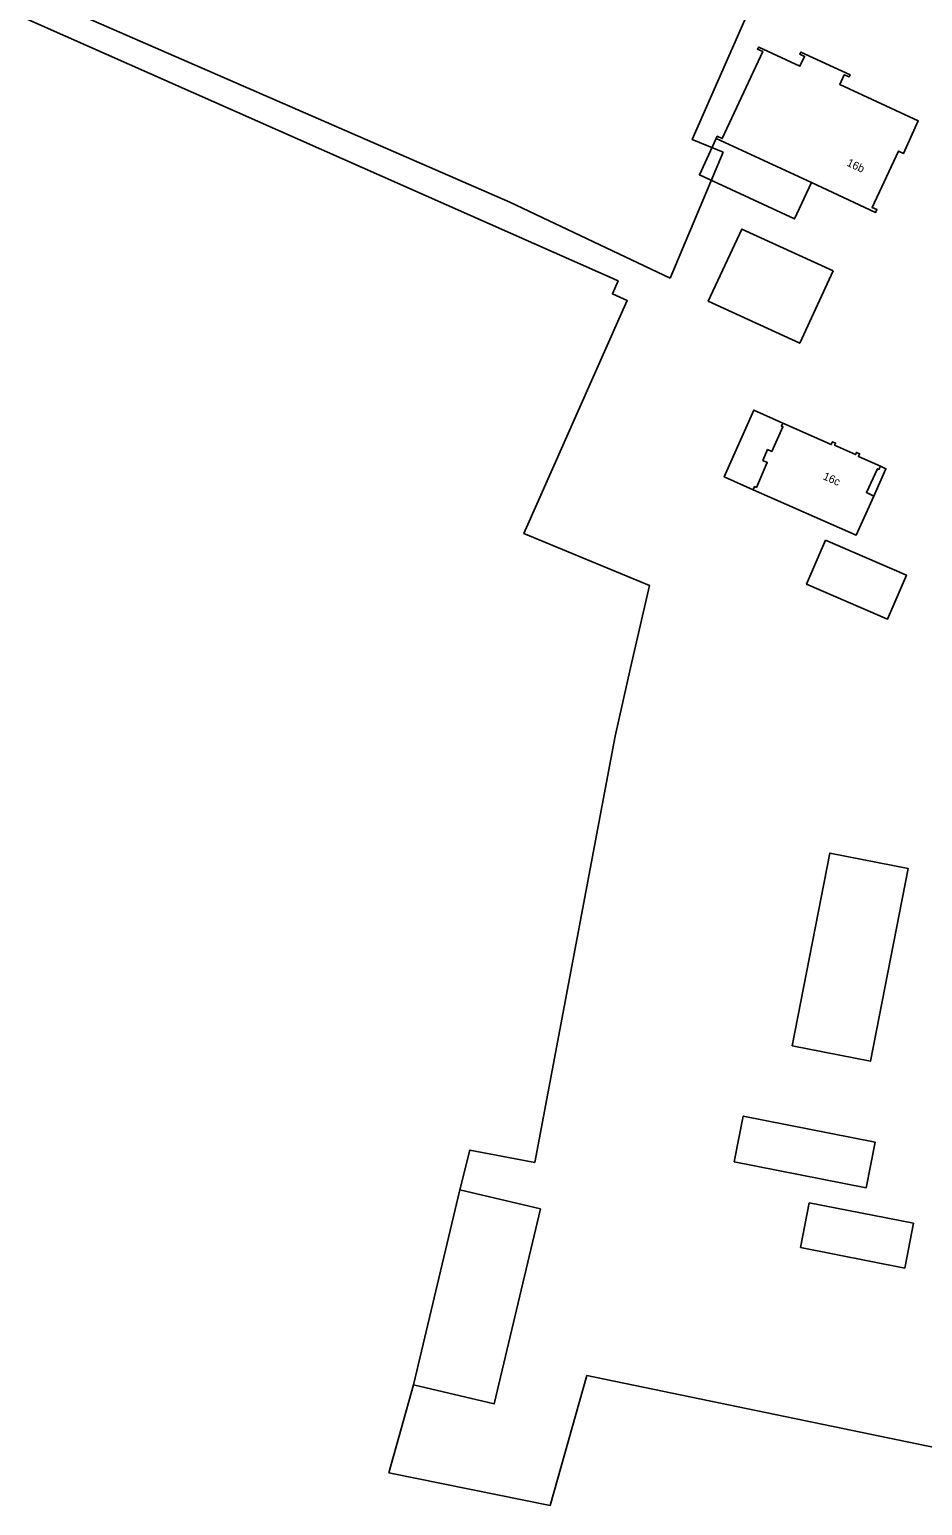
# Model space of a CAD drawing. Extents: x 136000 to 141000, y 400494 to 402006.
# Drawn here: x 137065.4 to 137177.1, y 401403.3 to 401587.8 of the extents above; entities that cross this region are included whole.
import ezdxf

# ---------------------------------------------------------------- set-up
doc = ezdxf.new("R2010")
doc.units = 0
for name, color, linetype in [('gg-afsc-draadraster', 7, 'Continuous'), ('gg-afsc-lijn draadraster', 7, 'Continuous'), ('gg-anno-huisnummerreeks BGT', 7, 'Continuous'), ('gg-bbg-bijgebouw', 7, 'Continuous'), ('gg-bbg-gedigitaliseerde bijgebouw', 7, 'Continuous'), ('gg-bbg-hoofdgebouw', 7, 'Continuous'), ('gg-bbg-luifel en loopbrug', 7, 'Continuous'), ('gg-bbg-open loods', 7, 'Continuous'), ('gg-knt-bronhoudergrens', 7, 'Continuous'), ('gt-bbg-plantopografie pand', 7, 'Continuous'), ('gt-grn-vlakafsluiter', 7, 'Continuous')]:
    doc.layers.add(name, color=color, linetype=linetype)

msp = doc.modelspace()

# ---------------------------------------------------------------- linework, layer by layer
at = {"layer": 'gg-afsc-draadraster'}
msp.add_line((137135.1, 401419.6), (137195.75, 401407.02), dxfattribs=at)
at = {"layer": 'gg-afsc-lijn draadraster'}
msp.add_line((137135.1, 401419.6), (137195.75, 401407.02), dxfattribs=at)
at = {"layer": 'gg-bbg-bijgebouw'}
msp.add_lwpolyline([(137165.9, 401557.62), (137161.72, 401548.59), (137150.29, 401553.83), (137154.47, 401562.85), (137165.9, 401557.62)], dxfattribs=at)
at = {"layer": 'gg-bbg-gedigitaliseerde bijgebouw'}
for points in [[(137160.76, 401460.78), (137170.56, 401458.86), (137175.29, 401482.94), (137165.49, 401484.87), (137160.76, 401460.78)], [(137161.8, 401435.57), (137162.9, 401441.16), (137175.94, 401438.6), (137174.84, 401433.01), (137161.8, 401435.57)]]:
    msp.add_lwpolyline(points, dxfattribs=at)
at = {"layer": 'gg-bbg-hoofdgebouw'}
msp.add_line((137151.28, 401574.17), (137163.18, 401568.65), dxfattribs=at)
for points in [[(137163.18, 401568.65), (137171.2, 401564.93), (137171.36, 401565.28), (137170.76, 401565.54), (137174.05, 401572.59), (137174.68, 401572.29), (137176.53, 401576.37), (137166.73, 401580.91), (137167.29, 401582.14), (137167.89, 401581.86), (137168.02, 401582.13), (137161.85, 401584.97), (137161.73, 401584.7), (137162.32, 401584.43), (137161.75, 401583.2), (137156.59, 401585.59), (137156.46, 401585.32), (137157.09, 401585.03), (137152.04, 401574.15), (137151.41, 401574.44), (137151.28, 401574.17)], [(137159.61, 401538.61), (137159.44, 401538.23), (137159.61, 401538.15), (137158.22, 401535.07), (137157.7, 401535.29), (137157.11, 401533.92), (137157.65, 401533.69), (137156.31, 401530.56), (137156.07, 401530.66), (137155.91, 401530.27)], [(137171.8, 401533.2), (137169.05, 401534.42), (137169.21, 401534.78), (137168.83, 401534.94), (137168.71, 401534.67), (137166.08, 401535.85), (137166.2, 401536.11), (137165.82, 401536.27), (137165.67, 401535.92), (137159.61, 401538.61)], [(137170.97, 401529.48), (137170.05, 401529.91), (137171.46, 401532.9), (137171.63, 401532.82), (137171.8, 401533.2)], [(137155.91, 401530.27), (137168.79, 401524.6), (137170.97, 401529.48)]]:
    msp.add_lwpolyline(points, dxfattribs=at)
at = {"layer": 'gg-bbg-luifel en loopbrug'}
for points in [[(137151.28, 401574.17), (137149.18, 401569.63), (137161.07, 401564.11), (137163.18, 401568.65)], [(137155.91, 401530.27), (137152.28, 401531.87), (137155.99, 401540.22), (137159.61, 401538.61)], [(137170.97, 401529.48), (137172.49, 401532.89), (137171.8, 401533.2)]]:
    msp.add_lwpolyline(points, dxfattribs=at)
at = {"layer": 'gg-bbg-open loods'}
msp.add_line((137119.23, 401442.8), (137113.43, 401418.4), dxfattribs=at)
for points in [[(137153.54, 401446.29), (137154.66, 401452), (137171.15, 401448.75), (137170.03, 401443.05), (137153.54, 401446.29)], [(137113.43, 401418.4), (137123.51, 401416.04), (137129.3, 401440.41), (137119.23, 401442.8)]]:
    msp.add_lwpolyline(points, dxfattribs=at)
at = {"layer": 'gg-knt-bronhoudergrens'}
for p, q in [((137152.13, 401572.45), (137145.53, 401556.71)), ((137138.63, 401499.47), (137128.61, 401446.22)), ((137130.51, 401403.34), (137135.1, 401419.6))]:
    msp.add_line(p, q, dxfattribs=at)
for points in [[(137040.75, 401603.11), (137035.6, 401605.35), (136954.37, 401641.77), (136916.84, 401660.23), (136915.67, 401657.84), (136997.85, 401618.86), (137139.02, 401556.38), (137138.3, 401554.75), (137140.14, 401553.93), (137139.26, 401551.95)], [(137138.63, 401499.47), (137140.57, 401508), (137142.92, 401518.32), (137127.23, 401524.8), (137139.26, 401551.95)], [(137119.23, 401442.8), (137120.48, 401447.75), (137128.61, 401446.22)], [(137113.43, 401418.4), (137110.35, 401407.4), (137130.51, 401403.34)]]:
    msp.add_lwpolyline(points, dxfattribs=at)
at = {"layer": 'gt-bbg-plantopografie pand'}
msp.add_lwpolyline([(137164.96, 401523.98), (137175.06, 401519.61), (137172.68, 401514.1), (137162.58, 401518.47), (137164.96, 401523.98)], dxfattribs=at)
at = {"layer": 'gt-grn-vlakafsluiter'}
for points in [[(137158.09, 401651.38), (137133.12, 401612.6), (137158.52, 401597.36), (137148.29, 401574.03), (137152.13, 401572.45)], [(137040.75, 401603.11), (137125.49, 401566.22), (137145.53, 401556.71)]]:
    msp.add_lwpolyline(points, dxfattribs=at)

# ---------------------------------------------------------------- texts
at = {"layer": 'gg-anno-huisnummerreeks BGT'}
for s, rotation, p in [('16b', 334.9, (137167.51, 401570.8)), ('16c', 335.9, (137164.54, 401531.61))]:
    msp.add_text(s, height=1, rotation=rotation, dxfattribs=at).set_placement(p)

doc.saveas('drawing.dxf')
